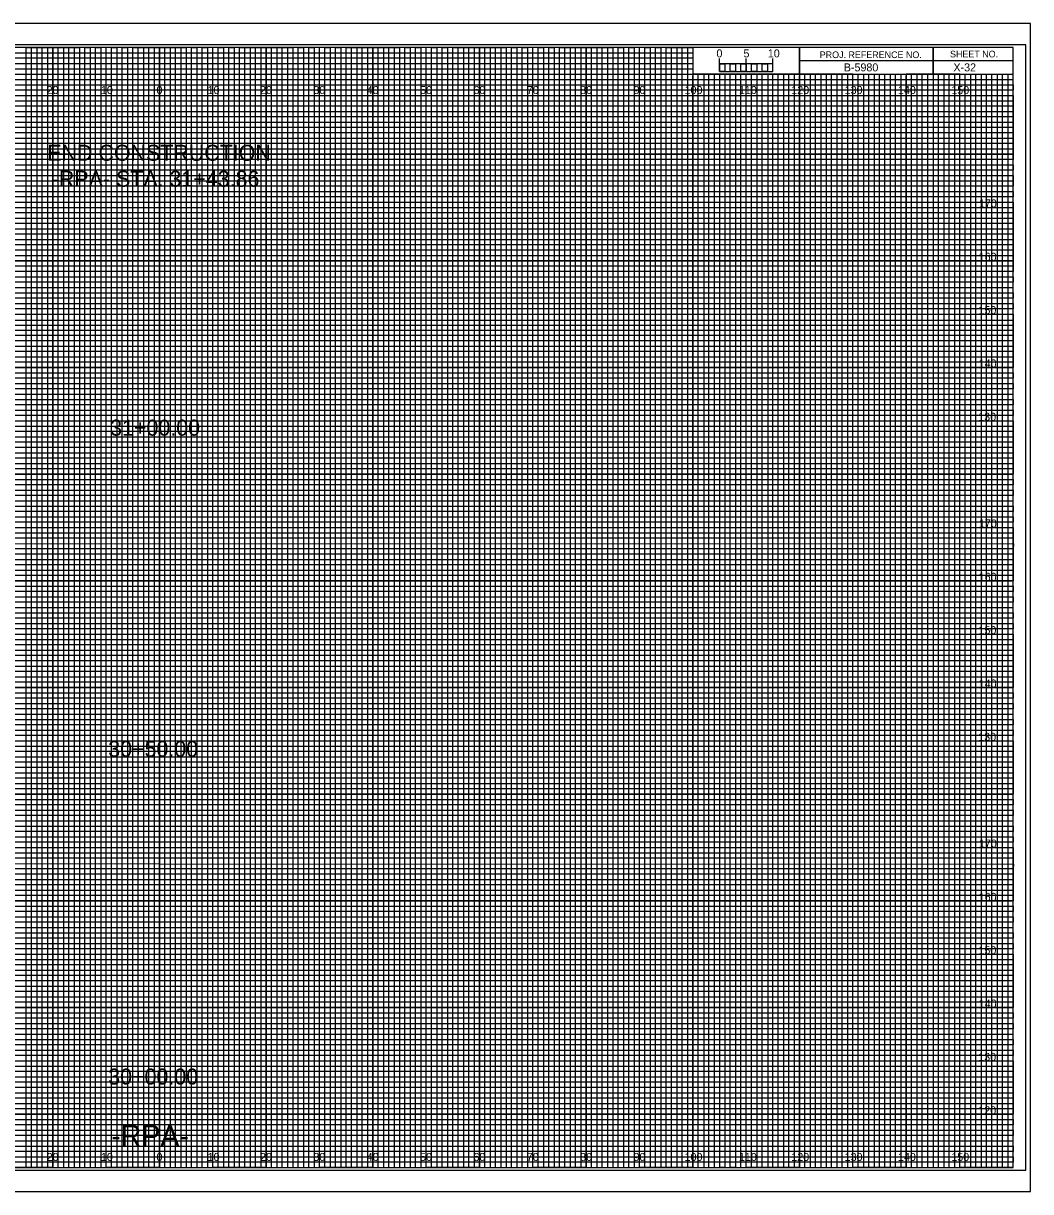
# Model space of a CAD drawing. Extents: x -13 to 323, y -5 to 1974.
# Drawn here: x 134.5 to 323.3, y 1755.5 to 1974.5 of the extents above; entities that cross this region are included whole.
import ezdxf

# ---------------------------------------------------------------- set-up
doc = ezdxf.new("R2010")
doc.units = 0
for name, color, linetype in [('Exist Cross Section Cell', 7, 'Continuous'), ('Exist XS Center Line Elevation Label', 7, 'Continuous'), ('Exist XS Ground Line', 7, 'Continuous'), ('Prop CMT Bridge Girder Bottom Critical Point Inside', 7, 'Continuous'), ('Prop CMT Guardrail Graphics', 7, 'Continuous'), ('Prop CMT Guardrail Widen Shoulder', 7, 'Continuous'), ('Prop CMT Pvmt Course 1', 7, 'Continuous'), ('Prop CMT Pvmt Course 2', 7, 'Continuous'), ('Prop CMT Pvmt Course 3', 7, 'Continuous'), ('Prop CMT Pvmt Surface', 7, 'Continuous'), ('Prop CMT Pvmt Surface Shoulder', 7, 'Continuous'), ('Prop CMT Shld Paved Course 1', 7, 'Continuous'), ('Prop CMT Shld Paved Course 2', 7, 'Continuous'), ('Prop CMT Shld Paved Course 3', 7, 'Continuous'), ('Prop CMT Slope Grass', 7, 'Continuous'), ('Prop CMT Subgrade Earthwork', 7, 'Continuous'), ('Scratch_Level_1', 7, 'Continuous')]:
    doc.layers.add(name, color=color, linetype=linetype)

msp = doc.modelspace()

# ---------------------------------------------------------------- linework, layer by layer
at = {"layer": 'Exist XS Center Line Elevation Label'}
for points in [[(125, 1760), (135, 1760), (135, 1970), (145, 1970), (145, 1760), (155, 1760), (155, 1970), (165, 1970), (165, 1760), (175, 1760), (175, 1970), (185, 1970), (185, 1760), (195, 1760), (195, 1970), (205, 1970), (205, 1760), (215, 1760), (215, 1970), (225, 1970), (225, 1760), (235, 1760), (235, 1970), (245, 1970), (245, 1760), (255, 1760), (255, 1970), (259.93, 1970), (260, 1970), (260, 1965), (264.99, 1965), (264.99, 1760), (275, 1760), (275, 1965), (285, 1965), (285, 1760), (295, 1760), (295, 1965), (305, 1965), (305, 1760), (315, 1760), (315, 1965)], [(0, 1965), (275, 1965)], [(0, 1945), (320, 1945), (320, 1955), (0, 1955)], [(0, 1925), (320, 1925), (320, 1935), (0, 1935)], [(0, 1905), (320, 1905), (320, 1915), (0, 1915)], [(0, 1885), (320, 1885), (320, 1895), (0, 1895)], [(0, 1865), (320, 1865), (320, 1875), (0, 1875)], [(0, 1845), (320, 1845), (320, 1855), (0, 1855)], [(0, 1825), (320, 1825), (320, 1835), (0, 1835)], [(0, 1805), (320, 1805), (320, 1815), (0, 1815)], [(0, 1785), (320, 1785), (320, 1795), (0, 1795)], [(0, 1765), (320, 1765), (320, 1775), (0, 1775)]]:
    msp.add_lwpolyline(points, dxfattribs=at)
at = {"layer": 'Exist XS Ground Line'}
for p, q in [((150, 1970), (140, 1970)), ((140, 1970), (140, 1760)), ((150, 1760), (150, 1970)), ((170, 1970), (160, 1970)), ((160, 1970), (160, 1760)), ((170, 1760), (170, 1970)), ((190, 1970), (180, 1970)), ((180, 1970), (180, 1760)), ((190, 1760), (190, 1970)), ((210, 1970), (200, 1970)), ((200, 1970), (200, 1760)), ((210, 1760), (210, 1970)), ((230, 1970), (220, 1970)), ((220, 1970), (220, 1760)), ((230, 1760), (230, 1970)), ((250, 1970), (240, 1970)), ((240, 1970), (240, 1760)), ((250, 1760), (250, 1970)), ((260, 1970), (260, 1760)), ((270, 1760), (270, 1965)), ((290, 1965), (280, 1965)), ((280, 1965), (280, 1760)), ((290, 1760), (290, 1965)), ((310, 1965), (300, 1965)), ((300, 1965), (300, 1760)), ((310, 1760), (310, 1965)), ((140, 1760), (130, 1760)), ((160, 1760), (150, 1760)), ((180, 1760), (170, 1760)), ((200, 1760), (190, 1760)), ((220, 1760), (210, 1760)), ((240, 1760), (230, 1760)), ((260, 1760), (250, 1760)), ((280, 1760), (270, 1760)), ((300, 1760), (290, 1760)), ((320, 1760), (310, 1760)), ((320, 1760), (320, 1760))]:
    msp.add_line(p, q, dxfattribs=at)
for points in [[(0, 1960), (320, 1960), (320, 1950), (0, 1950)], [(0, 1940), (320, 1940), (320, 1930), (0, 1930)], [(0, 1920), (320, 1920), (320, 1910), (0, 1910)], [(0, 1900), (320, 1900), (320, 1890), (0, 1890)], [(0, 1880), (320, 1880), (320, 1870), (0, 1870)], [(0, 1860), (320, 1860), (320, 1850), (0, 1850)], [(0, 1840), (320, 1840), (320, 1830), (0, 1830)], [(0, 1820), (320, 1820), (320, 1810), (0, 1810)], [(0, 1800), (320, 1800), (320, 1790), (0, 1790)], [(0, 1780), (320, 1780), (320, 1770), (0, 1770)]]:
    msp.add_lwpolyline(points, dxfattribs=at)
at = {"layer": 'Prop CMT Pvmt Course 2'}
for p, q in [((265, 1965.49), (265, 1967.9)), ((265, 1966.9), (265, 1967.9)), ((270, 1965.49), (270, 1967.9)), ((275, 1965.49), (275, 1967.9)), ((275, 1966.9), (275, 1967.9))]:
    msp.add_line(p, q, dxfattribs=at)
for points in [[(275, 1966.9), (265, 1966.9), (265, 1965.49), (275, 1965.49)], [(265, 1966.9), (266, 1966.9), (266, 1965.49), (265, 1965.49)], [(267, 1966.9), (268, 1966.9), (268, 1965.49), (267, 1965.49)], [(269, 1966.9), (270, 1966.9), (270, 1965.49), (269, 1965.49)], [(271, 1966.9), (272, 1966.9), (272, 1965.49), (271, 1965.49)], [(273, 1966.9), (274, 1966.9), (274, 1965.49), (273, 1965.49)]]:
    msp.add_lwpolyline(points, close=True, dxfattribs=at)
at = {"layer": 'Prop CMT Pvmt Course 3'}
msp.add_lwpolyline([(-13.4, 1755.5), (323.3, 1755.5), (323.3, 1974.5), (-13.4, 1974.5)], close=True, dxfattribs=at)
at = {"layer": 'Prop CMT Pvmt Surface'}
for p, q in [((140, 1760), (140, 1970)), ((150, 1760), (150, 1970)), ((160, 1760), (160, 1970)), ((170, 1760), (170, 1970)), ((180, 1760), (180, 1970)), ((190, 1760), (190, 1970)), ((200, 1760), (200, 1970)), ((210, 1760), (210, 1970)), ((220, 1760), (220, 1970)), ((230, 1760), (230, 1970)), ((240, 1760), (240, 1970)), ((250, 1760), (250, 1970)), ((260, 1760), (260, 1964.69)), ((270, 1760), (270, 1964.69)), ((280, 1760), (280, 1964.69)), ((290, 1760), (290, 1964.69)), ((300, 1760), (300, 1964.69)), ((310, 1760), (310, 1964.69)), ((0, 1960), (320, 1960)), ((0, 1950), (320, 1950)), ((0, 1940), (320, 1940)), ((0, 1930), (320, 1930)), ((0, 1920), (320, 1920)), ((0, 1910), (320, 1910)), ((0, 1900), (320, 1900)), ((0, 1890), (320, 1890)), ((0, 1880), (320, 1880)), ((0, 1870), (320, 1870)), ((0, 1860), (320, 1860)), ((0, 1850), (320, 1850)), ((0, 1840), (320, 1840)), ((0, 1830), (320, 1830)), ((0, 1820), (320, 1820)), ((0, 1810), (320, 1810)), ((0, 1800), (320, 1800)), ((0, 1790), (320, 1790)), ((0, 1780), (320, 1780)), ((0, 1770), (320, 1770))]:
    msp.add_line(p, q, dxfattribs=at)
at = {"layer": 'Prop CMT Pvmt Surface Shoulder'}
for p, q in [((323.3, 1974.5), (-13.4, 1974.5)), ((-13.4, 1755.5), (323.3, 1755.5))]:
    msp.add_line(p, q, dxfattribs=at)
at = {"layer": 'Prop CMT Shld Paved Course 1'}
for p, q in [((0, 1969), (260, 1969)), ((260, 1969), (260, 1967.98)), ((260, 1967.98), (0, 1967.98)), ((0, 1967), (260, 1967)), ((260, 1967), (260, 1965.89)), ((260, 1965.89), (0, 1965.89)), ((0, 1964), (320, 1964))]:
    msp.add_line(p, q, dxfattribs=at)
for points in [[(0, 1963), (270, 1963), (320, 1963), (320, 1962), (0, 1962)], [(0, 1961), (320, 1961), (320, 1959), (0, 1959)], [(0, 1958), (320, 1958), (320, 1957), (0, 1956.98)], [(0, 1956), (320, 1956), (320, 1954), (0, 1954)], [(0, 1953), (320, 1953), (320, 1952), (0, 1952)], [(0, 1951), (320, 1951), (320, 1949), (0, 1949)], [(0, 1948), (320, 1948), (320, 1947), (0, 1947)], [(0, 1946), (320, 1946), (320, 1944), (0, 1944)], [(0, 1943), (320, 1943), (320, 1942), (0, 1942)], [(0, 1941), (320, 1941), (320, 1939), (0, 1939)], [(0, 1938), (320, 1938), (320, 1937), (0, 1937)], [(0, 1936), (320, 1936), (320, 1933.95), (320, 1933), (320, 1932), (0, 1932)], [(0, 1934), (320, 1934), (320, 1933), (0, 1933)], [(0, 1931), (320, 1931), (320, 1929), (0, 1929.03)], [(0, 1929.03), (320, 1929), (320, 1928), (0, 1928)], [(0, 1927), (320, 1927), (320, 1926), (0, 1926)], [(0, 1924), (320, 1924), (320, 1923), (0, 1923)], [(0, 1922), (320, 1922), (320, 1921), (0, 1921)], [(-0.07, 1918.89), (320, 1918.89), (320, 1917.88), (-0.07, 1917.88)], [(0, 1917), (320, 1917), (320, 1916), (0, 1916)], [(0, 1914), (320, 1914), (320, 1913), (0, 1913)], [(0, 1912), (320, 1912), (320, 1911), (0, 1911)], [(0, 1909), (320, 1909), (320, 1908), (0, 1908)], [(0, 1907), (320, 1907), (320, 1906), (0, 1906)], [(0, 1904), (320, 1904), (320, 1903), (0, 1903)], [(0, 1902), (320, 1902), (320, 1901), (0, 1901)], [(0, 1899), (320, 1899), (319.99, 1897.98), (0, 1898)], [(0, 1897), (320, 1897), (320, 1896), (0, 1896)], [(0, 1894), (320, 1894), (320, 1893), (0, 1893)], [(0, 1892), (320, 1892), (320, 1891), (0, 1891)], [(0, 1889), (320, 1889), (320, 1888), (0, 1888)], [(0, 1887), (320, 1887), (320, 1886), (0, 1886)], [(0, 1884), (320, 1884), (320, 1883), (0, 1883)], [(0, 1882), (320, 1882), (320, 1881), (0, 1881)], [(0, 1879), (320, 1879), (320, 1878), (0, 1878)], [(0, 1876.99), (320.07, 1876.91), (320, 1876), (0, 1876)], [(0, 1874), (320, 1874), (320, 1873), (0, 1873)], [(0, 1872), (320, 1872), (320, 1871), (0, 1871)], [(0, 1869), (320, 1869), (320, 1868), (0, 1868)], [(0, 1867), (320, 1867), (320, 1866), (0, 1866)], [(0, 1864), (320, 1864), (320, 1863), (0, 1863)], [(0, 1862), (320, 1862), (320, 1861), (0, 1861)], [(0, 1859), (320, 1859), (320, 1858), (0, 1858)], [(0, 1857), (320, 1857), (320, 1856), (0, 1856)], [(0, 1854), (320, 1854), (320, 1853), (0, 1853)], [(0, 1852), (320, 1852), (320, 1851), (0, 1851)], [(0, 1849), (320, 1849), (320, 1848), (0, 1848)], [(0, 1847), (320, 1847), (320, 1846), (0, 1846)], [(0, 1844), (320, 1844), (320, 1843), (0, 1843)], [(0, 1842), (320, 1842), (320, 1841), (0, 1841)], [(0, 1839), (320, 1839), (319.99, 1837.98), (0, 1838)], [(0, 1837), (320, 1837), (320, 1836), (0, 1836)], [(0, 1834), (320, 1834), (320, 1833), (0, 1833)], [(0, 1832), (320, 1832), (320, 1831), (0, 1831)], [(0, 1829), (320, 1829), (320, 1828), (0, 1828)], [(0, 1827), (320, 1827), (320, 1826), (0, 1826)], [(0, 1824), (320, 1824), (320, 1823), (0, 1823)], [(0, 1822), (320, 1822), (320, 1821), (0, 1821)], [(0, 1819), (320, 1819), (320, 1818), (0, 1818)], [(0, 1816.99), (320.07, 1816.91), (320, 1816), (0, 1816)], [(0, 1814), (320, 1814), (320, 1813), (0, 1813)], [(0, 1812), (320, 1812), (320, 1811), (0, 1811)], [(0, 1809), (320, 1809), (320, 1808), (0, 1808)], [(0, 1807), (320, 1807), (320, 1806), (0, 1806)], [(0, 1804), (320, 1804), (320, 1803), (0, 1803)], [(0, 1802), (320, 1802), (320, 1801), (0, 1801)], [(0, 1799), (320, 1799), (320, 1798), (0, 1798)], [(0, 1797), (320, 1797), (320, 1796), (0, 1796)], [(0, 1794), (320, 1794), (320, 1793), (0, 1793)], [(0, 1792), (320, 1792), (320, 1791), (0, 1791)], [(0, 1789), (320, 1789), (320, 1788), (0, 1788)], [(0, 1787), (320, 1787), (320, 1786), (0, 1786)], [(0, 1784), (320, 1784), (320, 1783), (0, 1783)], [(0, 1782), (320, 1782), (320, 1781), (0, 1781)], [(0, 1779), (320, 1779), (320, 1778), (0, 1778)], [(0, 1777), (320, 1777), (320, 1776), (0, 1776)], [(0, 1774), (320, 1774), (320, 1773), (0, 1773)], [(0, 1772), (320, 1772), (320, 1771), (0, 1771)], [(0, 1769), (320, 1769), (320, 1768), (0, 1768)], [(0, 1767), (320, 1767), (320, 1766), (0, 1766)], [(0, 1764), (320, 1764), (320, 1763), (0, 1763)], [(0, 1762), (320, 1762), (320, 1761), (0, 1761)]]:
    msp.add_lwpolyline(points, dxfattribs=at)
at = {"layer": 'Prop CMT Shld Paved Course 2'}
for p, q in [((305, 1970), (305, 1965)), ((305, 1965), (305, 1970)), ((280, 1967.5), (280, 1965)), ((320, 1967.49), (280, 1967.49)), ((280, 1965), (320, 1965))]:
    msp.add_line(p, q, dxfattribs=at)
for points in [[(320, 1970), (0, 1970), (0, 1760), (320, 1760)], [(280, 1970), (260, 1970), (260, 1965.03), (280, 1965.03)], [(320, 1970), (280, 1970), (280, 1965), (320, 1965)]]:
    msp.add_lwpolyline(points, close=True, dxfattribs=at)
at = {"layer": 'Prop CMT Shld Paved Course 3'}
for p, q in [((267, 1965), (266.01, 1965)), ((266.01, 1965), (266.01, 1760)), ((267, 1760), (267, 1965)), ((269, 1965), (268, 1965)), ((268, 1965), (268, 1760)), ((269, 1760), (269, 1965)), ((266.01, 1760), (265, 1760)), ((268, 1760), (267, 1760))]:
    msp.add_line(p, q, dxfattribs=at)
for points in [[(135, 1760), (136, 1760), (136, 1970), (137, 1970), (137, 1760)], [(137, 1760), (138, 1760), (138, 1970), (139, 1970), (139, 1760)], [(140, 1760), (141, 1760), (141, 1970), (142, 1970), (142, 1760)], [(142, 1760), (143, 1760), (143, 1970), (144, 1970), (144, 1760)], [(145, 1760), (146, 1760), (146, 1970), (147, 1970), (147, 1760)], [(147, 1760), (148, 1760), (148, 1970), (149, 1970), (149, 1760)], [(150, 1760), (151, 1760), (151, 1970), (152, 1970), (152, 1760)], [(152, 1760), (153, 1760), (153, 1970), (154, 1970), (154, 1760)], [(155, 1760), (156, 1760), (156, 1970), (157, 1970), (157, 1760)], [(157, 1760), (158, 1760), (158, 1970), (159, 1970), (159, 1760)], [(160, 1760), (161, 1760), (161, 1970), (162, 1970), (162, 1760)], [(162, 1760), (163, 1760), (163, 1970), (164, 1970), (164, 1760)], [(165, 1760), (166, 1760), (166, 1970), (167, 1970), (167, 1760)], [(167, 1760), (168, 1760), (168, 1970), (169, 1970), (169, 1760)], [(170, 1760), (171, 1760), (171, 1970), (172, 1970), (172, 1760)], [(172, 1760), (173, 1760), (173, 1970), (174, 1970), (174, 1760)], [(175, 1760), (176, 1760), (176, 1970), (177, 1970), (177, 1760)], [(177, 1760), (178, 1760), (178, 1970), (179, 1970), (179, 1760)], [(180, 1760), (181, 1760), (181, 1970), (182, 1970), (182, 1760)], [(182, 1760), (183, 1760), (183, 1970), (184, 1970), (184, 1760)], [(185, 1760), (186, 1760), (186, 1970), (187, 1970), (187, 1760)], [(187, 1760), (188, 1760), (188, 1970), (189, 1970), (189, 1760)], [(190, 1760), (191, 1760), (191, 1970), (192, 1970), (192, 1760)], [(192, 1760), (193, 1760), (193, 1970), (194, 1970), (194, 1760)], [(195, 1760), (196, 1760), (196, 1970), (197, 1970), (197, 1760)], [(197, 1760), (198, 1760), (198, 1970), (199, 1970), (199, 1760)], [(200, 1760), (201, 1760), (201, 1970), (202, 1970), (202, 1760)], [(202, 1760), (203, 1760), (203, 1970), (204, 1970), (204, 1760)], [(205, 1760), (206, 1760), (206, 1970), (207, 1970), (207, 1760)], [(207, 1760), (208, 1760), (208, 1970), (209, 1970), (209, 1760)], [(210, 1760), (211, 1760), (211, 1970), (212, 1970), (212, 1760)], [(212, 1760), (213, 1760), (213, 1970), (214, 1970), (214, 1760)], [(215, 1760), (216, 1760), (216, 1970), (217, 1970), (217, 1760)], [(217, 1760), (218, 1760), (218, 1970), (219, 1970), (219, 1760)], [(220, 1760), (221, 1760), (221, 1970), (222, 1970), (222, 1760)], [(222, 1760), (223, 1760), (223, 1970), (224, 1970), (224, 1760)], [(225, 1760), (226, 1760), (226, 1970), (227, 1970), (227, 1760)], [(227, 1760), (228, 1760), (228, 1970), (229, 1970), (229, 1760)], [(230, 1760), (231, 1760), (231, 1970), (232, 1970), (232, 1760)], [(232, 1760), (233, 1760), (233, 1970), (234, 1970), (234, 1760)], [(235, 1760), (236, 1760), (236, 1970), (237, 1970), (237, 1760)], [(237, 1760), (238, 1760), (238, 1970), (239, 1970), (239, 1760)], [(240, 1760), (241, 1760), (241, 1970), (242, 1970), (242, 1760)], [(242, 1760), (243, 1760), (243, 1970), (244, 1970), (244, 1760)], [(245, 1760), (246, 1760), (246, 1970), (247, 1970), (247, 1760)], [(247, 1760), (248, 1760), (248, 1970), (249, 1970), (249, 1760)], [(250, 1760), (251, 1760), (251, 1970), (252, 1970), (252, 1760)], [(252, 1760), (253, 1760), (253, 1970), (254, 1970), (254, 1760)], [(255, 1760), (256, 1760), (256, 1970), (257, 1970), (257, 1760)], [(257, 1760), (258, 1760), (258, 1970), (259, 1970), (259, 1760)], [(260, 1760), (261, 1760), (261, 1965), (262.02, 1965), (262.02, 1760)], [(262, 1760), (263, 1760), (263, 1965), (263.99, 1965), (263.99, 1760)], [(270, 1760), (270.98, 1760), (270.98, 1965), (272, 1965), (272, 1760)], [(272, 1760), (273, 1760), (273, 1965), (274.05, 1965), (274.05, 1760)], [(275, 1760), (276, 1760), (276, 1965), (277, 1965), (277, 1760)], [(277, 1760), (278, 1760), (278, 1965), (279, 1965), (279, 1760)], [(280, 1760), (281, 1760), (281, 1965), (282, 1965), (282, 1760)], [(282, 1760), (283, 1760), (283, 1965), (284, 1965), (284, 1760)], [(285, 1760), (286, 1760), (286, 1965), (287, 1965), (287, 1760)], [(287, 1760), (288, 1760), (288, 1965), (289, 1965), (289, 1760)], [(290, 1760), (291, 1760), (291, 1965), (292, 1965), (292, 1760)], [(292, 1760), (293, 1760), (293, 1965), (294, 1965), (294, 1760)], [(295, 1760), (296, 1760), (296, 1965), (297, 1965), (297, 1760)], [(297, 1760), (298, 1760), (298, 1965), (299, 1965), (299, 1760)], [(300, 1760), (301, 1760), (301, 1965), (302, 1965), (302, 1760)], [(302, 1760), (303, 1760), (303, 1965), (304, 1965), (304, 1760)], [(305, 1760), (306, 1760), (306, 1965), (307, 1965), (307, 1760)], [(307, 1760), (308, 1760), (308, 1965), (309, 1965), (309, 1760)], [(310, 1760), (311, 1760), (311, 1965), (312, 1965), (312, 1760)], [(312, 1760), (313, 1760), (313, 1965), (314, 1965), (314, 1760)], [(315, 1760), (316, 1760), (316, 1965), (317, 1965), (317, 1760)], [(317, 1760), (318, 1760), (318, 1965), (319, 1965), (319, 1760)]]:
    msp.add_lwpolyline(points, dxfattribs=at)
at = {"layer": 'Prop CMT Subgrade Earthwork'}
msp.add_lwpolyline([(-10.8, 1759.5), (322.4, 1759.5), (322.4, 1970.5), (-10.8, 1970.5)], close=True, dxfattribs=at)

# ---------------------------------------------------------------- texts
at = {"layer": 'Exist Cross Section Cell'}
for s, p in [('20', (138.86, 1961.25)), ('10', (149.04, 1961.25)), ('0', (159.45, 1961.25)), ('0', (159.45, 1961.25)), ('10', (169.04, 1961.25)), ('20', (178.86, 1961.25)), ('30', (188.86, 1961.25)), ('40', (198.86, 1961.25)), ('50', (208.86, 1961.25)), ('60', (218.86, 1961.25)), ('70', (228.86, 1961.25)), ('80', (238.86, 1961.25)), ('90', (248.86, 1961.25)), ('100', (258.44, 1961.25)), ('110', (268.62, 1961.25)), ('120', (278.44, 1961.25)), ('130', (288.44, 1961.25)), ('140', (298.44, 1961.25)), ('150', (308.44, 1961.25)), ('20', (138.86, 1761.25)), ('10', (149.04, 1761.25)), ('0', (159.45, 1761.25)), ('0', (159.45, 1761.25)), ('10', (169.04, 1761.25)), ('20', (178.86, 1761.25)), ('30', (188.86, 1761.25)), ('40', (198.86, 1761.25)), ('50', (208.86, 1761.25)), ('60', (218.86, 1761.25)), ('70', (228.86, 1761.25)), ('80', (238.86, 1761.25)), ('90', (248.86, 1761.25)), ('100', (258.44, 1761.25)), ('110', (268.62, 1761.25)), ('120', (278.44, 1761.25)), ('130', (288.44, 1761.25)), ('140', (298.44, 1761.25)), ('150', (308.44, 1761.25))]:
    msp.add_text(s, height=1.5, dxfattribs=at).set_placement(p)
at = {"layer": 'Prop CMT Bridge Girder Bottom Critical Point Inside'}
for s, p in [('5', (269.47, 1968.12)), ('10', (274.04, 1968.12))]:
    msp.add_text(s, height=1.5, dxfattribs=at).set_placement(p)
at = {"layer": 'Prop CMT Guardrail Graphics'}
msp.add_text('B-5980', height=1.5, dxfattribs=at).set_placement((288.28, 1965.5))
at = {"layer": 'Prop CMT Guardrail Widen Shoulder'}
msp.add_text('X-32', height=1.5, dxfattribs=at).set_placement((308.83, 1965.5))
at = {"layer": 'Prop CMT Pvmt Course 1'}
for s, p in [('170', (313.61, 1940)), ('160', (313.57, 1930)), ('150', (313.52, 1920)), ('140', (313.57, 1910)), ('130', (313.49, 1900)), ('170', (313.61, 1880)), ('160', (313.57, 1870)), ('150', (313.52, 1860)), ('140', (313.57, 1850)), ('130', (313.49, 1840)), ('170', (313.61, 1820)), ('160', (313.57, 1810)), ('150', (313.52, 1800)), ('140', (313.57, 1790)), ('130', (313.49, 1780)), ('120', (313.5, 1770))]:
    msp.add_text(s, height=1.5, dxfattribs=at).set_placement(p)
at = {"layer": 'Prop CMT Pvmt Course 2'}
msp.add_text('0', height=1.5, dxfattribs=at).set_placement((264.41, 1968.12))
at = {"layer": 'Prop CMT Shld Paved Course 2'}
for s, p in [('PROJ. REFERENCE NO.', (283.77, 1967.99)), ('SHEET NO.', (308.19, 1968.12))]:
    msp.add_text(s, height=1.25, dxfattribs=at).set_placement(p)
at = {"layer": 'Prop CMT Slope Grass'}
for s, p in [('END CONSTRUCTION', (138.99, 1948.74)), ('-RPA- STA. 31+43.86', (139.83, 1943.87)), ('31+00.00', (150.77, 1897.21)), ('30+50.00', (150.41, 1837)), ('30+00.00', (150.41, 1775.57))]:
    msp.add_text(s, height=3, dxfattribs=at).set_placement(p)
at = {"layer": 'Scratch_Level_1'}
msp.add_text('-RPA-', height=4, dxfattribs=at).set_placement((150.97, 1764))

doc.saveas('drawing.dxf')
